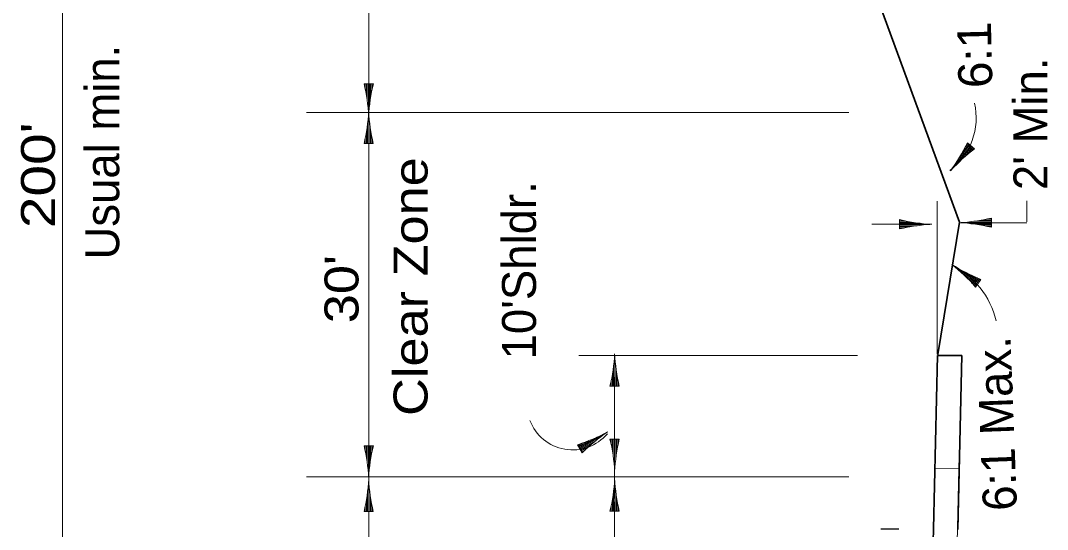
# Model space of a CAD drawing. Extents: x 2363427 to 2368559, y 6957299 to 6980140.
# Drawn here: x 2365735.6 to 2366158.6, y 6959418.5 to 6959628 of the extents above; entities that cross this region are included whole.
import ezdxf
from ezdxf.enums import TextEntityAlignment as Align

# ---------------------------------------------------------------- set-up
doc = ezdxf.new("R2010")
doc.units = 0
doc.header["$LTSCALE"] = 5.6
doc.layers.add('3', color=7, linetype='Continuous', lineweight=35)
doc.layers.add('4', color=7, linetype='Continuous', lineweight=13)

msp = doc.modelspace()

# ---------------------------------------------------------------- linework, layer by layer
at = {"layer": '3'}
for p, q in [((2366020.057, 6959823.292), (2366122.404, 6959545.045)), ((2366113.384, 6959490.523), (2366122.404, 6959545.045)), ((2366123.293, 6959490.203), (2366113.29, 6959490.203)), ((2366121.622, 6959418.539), (2366123.29, 6959490.086))]:
    msp.add_line(p, q, dxfattribs=at)
msp.add_lwpolyline([(2366108.492, 6959298.906), (2366111.624, 6959418.772), (2366113.29, 6959490.203)], dxfattribs=at)
at = {"layer": '3', "lineweight": 13}
for points in [[(2366112.295, 6959443.633), (2366122.156, 6959443.473), (2366123.293, 6959490.203), (2366113.29, 6959490.203)], [(2366105.871, 6959163.407), (2366115.727, 6959163.264), (2366122.156, 6959443.473), (2366112.295, 6959443.633)]]:
    msp.add_lwpolyline(points, close=True, dxfattribs=at)
at = {"layer": '4'}
for p, q in [((2365752.938, 6959093.641), (2365752.938, 6960118.953)), ((2365879.004, 6959590.203), (2365879.074, 6959824.364)), ((2365877.086, 6959602.007), (2365880.916, 6959602.007)), ((2365877.436, 6959602.007), (2365877.436, 6959600.423)), ((2365877.936, 6959602.007), (2365877.934, 6959597.731)), ((2365878.436, 6959602.007), (2365878.434, 6959594.657)), ((2365878.936, 6959602.007), (2365878.932, 6959589.443)), ((2365879.436, 6959602.007), (2365879.434, 6959593.397)), ((2365879.936, 6959602.007), (2365879.934, 6959597.145)), ((2365880.436, 6959602.007), (2365880.435, 6959599.625)), ((2366076.79, 6959590.203), (2365853.393, 6959590.203)), ((2365878.997, 6959440.203), (2365878.997, 6959590.203)), ((2365879.062, 6959577.368), (2365879.062, 6959589.932)), ((2365878.562, 6959577.368), (2365878.562, 6959585.977)), ((2365879.562, 6959577.368), (2365879.562, 6959584.718)), ((2365878.062, 6959577.368), (2365878.062, 6959582.23)), ((2365880.062, 6959577.368), (2365880.062, 6959581.645)), ((2365880.912, 6959577.368), (2365877.082, 6959577.368)), ((2365877.562, 6959577.368), (2365877.562, 6959579.749)), ((2365880.562, 6959577.368), (2365880.562, 6959578.953)), ((2366127.062, 6959576.505), (2366119.044, 6959566.832)), ((2366127.447, 6959576.186), (2366121.952, 6959569.557)), ((2366126.677, 6959576.824), (2366121.986, 6959571.165)), ((2366126.292, 6959577.143), (2366123.563, 6959573.851)), ((2366127.832, 6959575.867), (2366124.729, 6959572.123)), ((2366125.907, 6959577.462), (2366124.896, 6959576.242)), ((2366125.638, 6959577.685), (2366128.586, 6959575.241)), ((2366128.217, 6959575.547), (2366126.697, 6959573.714)), ((2365879.074, 6959568.525), (2365878.997, 6959568.953)), ((2366113.128, 6959490.729), (2366113.128, 6959553.665)), ((2366150.132, 6959545.17), (2366150.132, 6959553.814)), ((2366135.602, 6959546.387), (2366134.017, 6959546.387)), ((2366135.602, 6959546.737), (2366135.602, 6959542.907)), ((2366110.908, 6959544.155), (2366086.204, 6959544.155)), ((2366097.596, 6959542.239), (2366097.596, 6959546.069)), ((2366097.596, 6959542.239), (2366097.596, 6959546.069)), ((2366097.596, 6959545.589), (2366099.978, 6959545.589)), ((2366097.596, 6959545.589), (2366099.978, 6959545.589)), ((2366097.596, 6959545.089), (2366102.458, 6959545.089)), ((2366097.596, 6959545.089), (2366102.458, 6959545.089)), ((2366097.596, 6959544.589), (2366106.206, 6959544.589)), ((2366097.596, 6959544.589), (2366106.206, 6959544.589)), ((2366097.596, 6959544.089), (2366110.16, 6959544.089)), ((2366097.596, 6959544.089), (2366110.16, 6959544.089)), ((2366097.596, 6959543.589), (2366104.946, 6959543.589)), ((2366097.596, 6959543.589), (2366104.946, 6959543.589)), ((2366097.596, 6959543.089), (2366101.872, 6959543.089)), ((2366097.596, 6959543.089), (2366101.872, 6959543.089)), ((2366097.596, 6959542.589), (2366099.181, 6959542.589)), ((2366097.596, 6959542.589), (2366099.181, 6959542.589)), ((2366135.602, 6959544.887), (2366123.038, 6959544.887)), ((2366123.47, 6959544.822), (2366150.048, 6959544.822)), ((2366135.602, 6959544.387), (2366126.992, 6959544.387)), ((2366135.602, 6959545.387), (2366128.252, 6959545.387)), ((2366135.602, 6959543.887), (2366130.74, 6959543.887)), ((2366135.602, 6959545.887), (2366131.326, 6959545.887)), ((2366135.602, 6959543.387), (2366133.22, 6959543.387)), ((2366130.135, 6959519.943), (2366119.894, 6959527.223)), ((2366129.845, 6959519.536), (2366122.828, 6959524.524)), ((2366130.424, 6959520.351), (2366124.434, 6959524.609)), ((2366129.556, 6959519.128), (2366125.592, 6959521.945)), ((2366130.714, 6959520.759), (2366127.229, 6959523.236)), ((2366131.206, 6959521.451), (2366128.988, 6959518.329)), ((2366131.004, 6959521.166), (2366129.712, 6959522.084)), ((2366129.266, 6959518.721), (2366127.324, 6959520.101)), ((2366080.29, 6959490.203), (2365965.51, 6959490.203)), ((2365980.379, 6959477.573), (2365980.379, 6959490.137)), ((2365979.879, 6959477.573), (2365979.879, 6959486.183)), ((2365980.879, 6959477.573), (2365980.879, 6959484.923)), ((2365978.879, 6959477.573), (2365978.879, 6959479.955)), ((2365979.379, 6959477.573), (2365979.379, 6959482.435)), ((2365980.314, 6959431.224), (2365980.314, 6959481.252)), ((2365981.379, 6959477.573), (2365981.379, 6959481.85)), ((2365981.879, 6959477.573), (2365981.879, 6959479.159)), ((2365982.229, 6959477.573), (2365978.399, 6959477.573)), ((2365966.006, 6959451.689), (2365976.746, 6959458.209)), ((2365966.966, 6959450.108), (2365964.978, 6959453.382)), ((2365965.228, 6959452.971), (2365967.263, 6959454.207)), ((2365965.487, 6959452.545), (2365969.643, 6959455.067)), ((2365965.746, 6959452.117), (2365973.106, 6959456.585)), ((2365966.265, 6959451.262), (2365972.548, 6959455.076)), ((2365978.399, 6959455.664), (2365982.229, 6959455.664)), ((2365978.749, 6959455.664), (2365978.749, 6959454.079)), ((2365979.249, 6959455.664), (2365979.249, 6959451.387)), ((2365979.749, 6959455.664), (2365979.749, 6959448.314)), ((2365980.249, 6959455.664), (2365980.249, 6959443.1)), ((2365980.749, 6959455.664), (2365980.749, 6959447.055)), ((2365981.249, 6959455.664), (2365981.249, 6959450.802)), ((2365981.749, 6959455.664), (2365981.749, 6959453.283)), ((2365877.086, 6959452.994), (2365880.916, 6959452.993)), ((2365877.436, 6959452.994), (2365877.436, 6959451.409)), ((2365877.936, 6959452.994), (2365877.934, 6959448.717)), ((2365878.436, 6959452.993), (2365878.434, 6959445.644)), ((2365878.936, 6959452.993), (2365878.932, 6959440.429)), ((2365879.436, 6959452.993), (2365879.434, 6959444.383)), ((2365879.936, 6959452.993), (2365879.934, 6959448.131)), ((2365880.436, 6959452.993), (2365880.435, 6959450.611)), ((2365966.524, 6959450.835), (2365970.18, 6959453.053)), ((2365966.784, 6959450.407), (2365968.139, 6959451.23)), ((2366076.79, 6959440.203), (2365853.393, 6959440.203)), ((2365878.997, 6959211.297), (2365878.997, 6959440.203)), ((2365879.062, 6959425.89), (2365879.062, 6959438.454)), ((2365980.379, 6959426.05), (2365980.379, 6959438.614)), ((2365878.562, 6959425.89), (2365878.562, 6959434.499)), ((2365879.562, 6959425.89), (2365879.562, 6959433.24)), ((2365979.879, 6959426.05), (2365979.879, 6959434.659)), ((2365980.879, 6959426.05), (2365980.879, 6959433.4)), ((2365877.562, 6959425.89), (2365877.562, 6959428.271)), ((2365878.062, 6959425.89), (2365878.062, 6959430.752)), ((2365880.062, 6959425.89), (2365880.062, 6959430.167)), ((2365978.879, 6959426.05), (2365978.879, 6959428.431)), ((2365979.379, 6959426.05), (2365979.379, 6959430.912)), ((2365980.314, 6959171.25), (2365980.314, 6959429.906)), ((2365981.379, 6959426.05), (2365981.379, 6959430.327)), ((2365880.912, 6959425.89), (2365877.082, 6959425.89)), ((2365880.562, 6959425.89), (2365880.562, 6959427.475)), ((2365982.229, 6959426.05), (2365978.399, 6959426.05)), ((2365981.879, 6959426.05), (2365981.879, 6959427.635))]:
    msp.add_line(p, q, dxfattribs=at)
at = {"layer": '4', "lineweight": 25}
msp.add_line((2366089.976, 6959418.841), (2366097.321, 6959418.841), dxfattribs=at)
at = {"layer": '4'}
for centre, radius, start, end in [((2365806.872, 6959585.135), 72.212, 2.82649, 13.51254), ((2365951.12, 6959585.092), 72.212, 166.45333, 177.13938), ((2366102.214, 6959587.931), 27.012, 306.76831, 13.14994), ((2365806.873, 6959594.262), 72.212, 346.47039, 357.15644), ((2365951.121, 6959594.262), 72.212, 182.84356, 193.52961), ((2366060.803, 6959609.484), 72.212, 323.18777, 333.87382), ((2366171.858, 6959517.429), 72.212, 126.81461, 137.50066), ((2366118.708, 6959616.946), 72.212, 272.84356, 283.52961), ((2366114.49, 6959616.278), 72.212, 256.47039, 267.15644), ((2366114.49, 6959616.278), 72.212, 256.47039, 267.15644), ((2366114.49, 6959472.031), 72.212, 92.84356, 103.52961), ((2366114.49, 6959472.031), 72.212, 92.84356, 103.52961), ((2366118.708, 6959472.699), 72.212, 76.47039, 87.15644), ((2366103.457, 6959496.331), 34.94, 13.44028, 63.14536), ((2366158.115, 6959588.463), 72.212, 237.43652, 248.12257), ((2366074.541, 6959470.893), 72.212, 41.06336, 51.74941), ((2365908.19, 6959494.467), 72.212, 346.47039, 357.15644), ((2366052.438, 6959494.467), 72.212, 182.84356, 193.52961), ((2365962.972, 6959470.11), 18.823, 200.84978, 319.74384), ((2365942.986, 6959522.164), 72.212, 287.73061, 298.41666), ((2366017.84, 6959398.859), 72.212, 124.10378, 134.78983), ((2365908.19, 6959438.77), 72.212, 2.84356, 13.52961), ((2366052.438, 6959438.77), 72.212, 166.47039, 177.15644), ((2365806.872, 6959436.121), 72.212, 2.82649, 13.51254), ((2365951.119, 6959436.078), 72.212, 166.45333, 177.13938), ((2365806.873, 6959442.784), 72.212, 346.47039, 357.15644), ((2365951.121, 6959442.784), 72.212, 182.84356, 193.52961), ((2365908.19, 6959442.944), 72.212, 346.47039, 357.15644), ((2366052.438, 6959442.944), 72.212, 182.84356, 193.52961)]:
    msp.add_arc(centre, radius, start, end, dxfattribs=at)

# ---------------------------------------------------------------- texts
for s, rotation, width, p in [('6:1 Usual', 91.404, 1.05, (2366134.955, 6959641.906)), ("200'", 90, 1.25, (2365749.798, 6959564.325)), ('Clear Zone', 90, 1.15, (2365903.242, 6959518.507)), ("30'", 90, 1.15, (2365874.802, 6959517.463))]:
    msp.add_text(s, height=14, rotation=rotation, dxfattribs=dict(at, width=width)).set_placement(p, align=Align.CENTER)
for s, rotation, p in [('Usual min.', 90, (2365776.236, 6959573.868)), ("2' Min.", 90, (2366158.606, 6959585.522)), ("10'Shldr.", 90, (2365947.926, 6959525.189)), ('6:1 Max.', 92.174, (2366144.727, 6959462.327))]:
    msp.add_text(s, height=14, rotation=rotation, dxfattribs=at).set_placement(p, align=Align.CENTER)

doc.saveas('drawing.dxf')
